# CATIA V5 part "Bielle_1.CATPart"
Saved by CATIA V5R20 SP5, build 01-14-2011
Part number: Bielle_1
Publications: "Diametre_bielle_ext", "Diametre_bielle_int", "Largeur_bielle"
Bounding box of the stored display mesh (mm): x -32.171 to 78.853, y -48.789 to -26.713, z 6 to 9
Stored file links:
  D:\thinkmotion-MPB\Dropbox\IAO_2011\MMS_GR3\IAO_2011_1523_mkessler\mkessler\mkessler_IAO\mkessler_INIT\Bielle_1.CATPart
  C:\Users\MARLENE\Documents\IFMA\S3\IAO\Copie de CAO\Assemblage_final.CATProduct
  D:\thinkmotion-MPB\Dropbox\IAO_2011\MMS_GR3\IAO_2011_1523_mkessler\mkessler\mkessler_IAO\mkessler_INIT\Squelette_bielle_1.CATPart
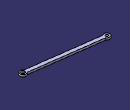
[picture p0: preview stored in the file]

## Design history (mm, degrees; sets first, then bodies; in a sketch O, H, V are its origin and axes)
Parameters
  Diametre_bielle_ext = 8 mm
  Diametre_bielle_int = 4 mm
  Largeur_bielle = 5 mm
  diametre_bielle_int = 8 mm
  diametre_bielle_ext = 4 mm
External parameters (linked from other documents)
  External.Longueur_bielle = 104 mm
Set1
  Plane1: linked copy from another document
  Point1: linked copy from another document
  Point2: linked copy from another document
  Line1: linked copy from another document
  Plane2: linked copy from another document
Body1 (main body)
  Sketch1 on Plane2, origin (0, 0, 6), H (1, 0, 0), V (0, 1, 0)
    arc A1 centre (74.862, -44.7925) radius 4 from (71.4297, -46.8467) to (72.1068, -41.8927) ccw
    reference projected point E1 (74.862, -44.7925) from Point1
    arc A2 centre (-28.18, -30.709) radius 4 from (-24.7477, -28.6549) to (-25.4248, -33.6088) ccw
    reference projected point E2 (-28.18, -30.709) from Point2
    circle A3 centre (74.862, -44.7925) radius 2.5
    reference projected point E3 (74.862, -44.7925) from Point1
    circle A4 centre (-28.18, -30.709) radius 2
    reference projected point E4 (-28.18, -30.709) from Point2
    line L1 (-24.7477, -28.6549) -> (72.1068, -41.8927)
    line L2 (-25.4248, -33.6088) -> (71.4297, -46.8467)
    reference projected line E5 (74.862, -44.7925) -> (-28.18, -30.709) from Line1
    reference projected line E6 (74.862, -44.7925) -> (-28.18, -30.709) from Line1
    reference projected line E7 (74.862, -44.7925) -> (-28.18, -30.709) from Line1
    radius A1 = 4 {= Diametre_bielle_ext /2}
    radius A2 = 4 {= Diametre_bielle_ext /2}
    radius A4 = 2 {= Diametre_bielle_int /2}
    distance L2 L1 = 5 {= Largeur_bielle}
    concentricity: A1 E1, A2 E2, A3 E3, A4 E4
    tangency: L2 A3
    parallelism: L2 E5, L1 E6
    symmetry: L1 L2 E7
  Pad1: profile Sketch1, direction (0, 0, 1), length 3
